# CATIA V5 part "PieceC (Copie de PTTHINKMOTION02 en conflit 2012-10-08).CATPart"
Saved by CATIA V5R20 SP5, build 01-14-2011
Part number: PieceC
Bounding box of the stored display mesh (mm): x -21 to 21, y -21 to 21, z -63 to 10
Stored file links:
  E:\IAO_2010\iao\IAO_MMS_Groupe2\IAO_MMS_Groupe2\melguidj\Catia\PieceC.CATPart
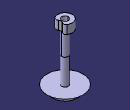
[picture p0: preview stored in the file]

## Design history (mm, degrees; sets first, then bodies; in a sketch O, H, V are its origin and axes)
Body1 (main body)
  Sketch1 on xy-plane, origin (0, 0, 0), H (1, 0, 0), V (0, 1, 0)
    point P1 (0, 0)
    point P2 (0, -12.5)
    circle A1 centre (0, 0) radius 4
    arc A2 centre (0, 0) radius 8.58 from (4.576, 7.2579) to (4.576, -7.2579) ccw
    axis line L1 (12.8244, 2.0574) -> (9.7271, 4.0102)
    point P5 (4.576, 7.2579)
    point P6 (4.576, -7.2579)
    arc A3 centre (2.7456, 4.3547) radius 3.432 from (4.576, 7.2579) to (5.3985, 2.1774) cw
    arc A4 centre (8.0513, 0) radius 3.432 from (5.3985, 2.1774) to (5.3985, -2.1774) ccw
    arc A5 centre (2.7456, -4.3547) radius 3.432 from (5.3985, -2.1774) to (4.576, -7.2579) cw
    point P12 (4.576, -7.2579)
    radius A1 = 4
    radius A2 = 8.58
    radius A3 = 3.432 {= Sketch1.radius(A5)}
    radius A4 = 3.432 {= Sketch1.radius(A5)}
    radius A5 = 3.432
    distance P5 V = 4.576 {= Sketch1.distance(P6 V)}
    distance P6 V = 4.576
    coincidence: P1 V, P2 V, P1 O, L1 P5, A5 P12, P12 A2
    tangency: L1 A2, A3 A2, A4 A3, A5 A4, A5 A2
    concentricity: A2 A1
  Pad1: profile Sketch1, direction (0, 0, 1), length 10
  Sketch2 on start face of Pad1, origin (0, 0, 0), H (1, 0, 0), V (0, -1, 0)
    circle A1 centre (0, 0) radius 4
    reference projected circle E1 centre (0, 0) radius 4 from edge [face of Pad1 from Sketch1.A1 | start face of Pad1]
    coincidence: A1 E1
  Pad2: profile Sketch2, direction (0, 0, -1), length 45
  Plane1: stored without definition
  DatumCurve1
  DatumCurve2
  Sketch3 on Plane1, origin (0, 0, 0), H (-0.2368, -0.9715, 0), V (0, 0, 1)
    point P1 (0, -26.0088)
    line L1 (0, -26.0088) -> (0, -63)
    line L2 (0, -63) -> (-14, -63)
    line L3 (-14, -63) -> (-21, -56)
    line L4 (-21, -56) -> (-4, -56)
    line L5 (-4, -56) -> (-4, -26.0088)
    line L6 (-4, -26.0088) -> (0, -26.0088)
    reference projected line E1 through (0, -77) direction (1, 0) from edge of DatumCurve2
    length L6 = 4
    angle L3 L2 = 45
    distance L2 E1 = 14
    distance L2 L4 = 7
    length L2 = 14
    coincidence: P1 V
    vertical: L1 V, L5 V
    horizontal: L2 H, L4 H, L6 H
  Shaft1: profile Sketch3, axis Sketch3.L1, angle 360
